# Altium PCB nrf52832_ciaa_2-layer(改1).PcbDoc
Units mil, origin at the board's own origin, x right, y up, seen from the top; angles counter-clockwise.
Board outline 354 x 353 mil, 2 copper layers (Top Layer, Bottom Layer), stack 11.8 mil thick; 15 components, 27 nets, 92 pads, 22 vias.
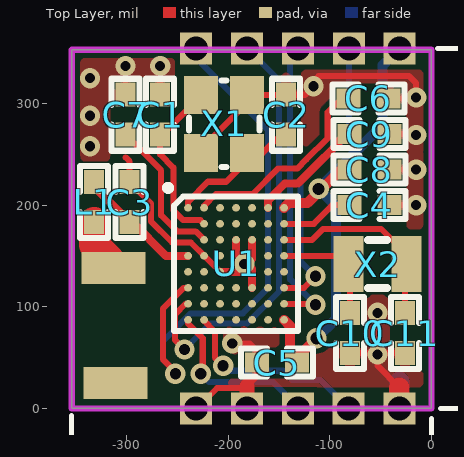
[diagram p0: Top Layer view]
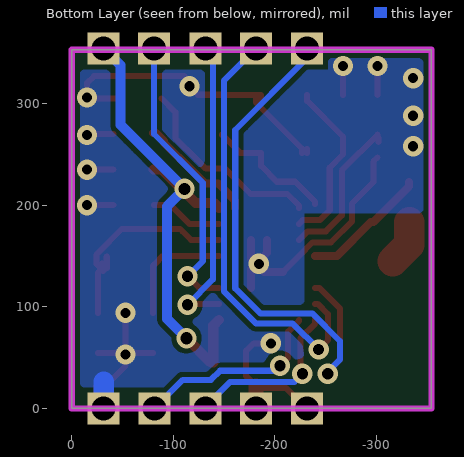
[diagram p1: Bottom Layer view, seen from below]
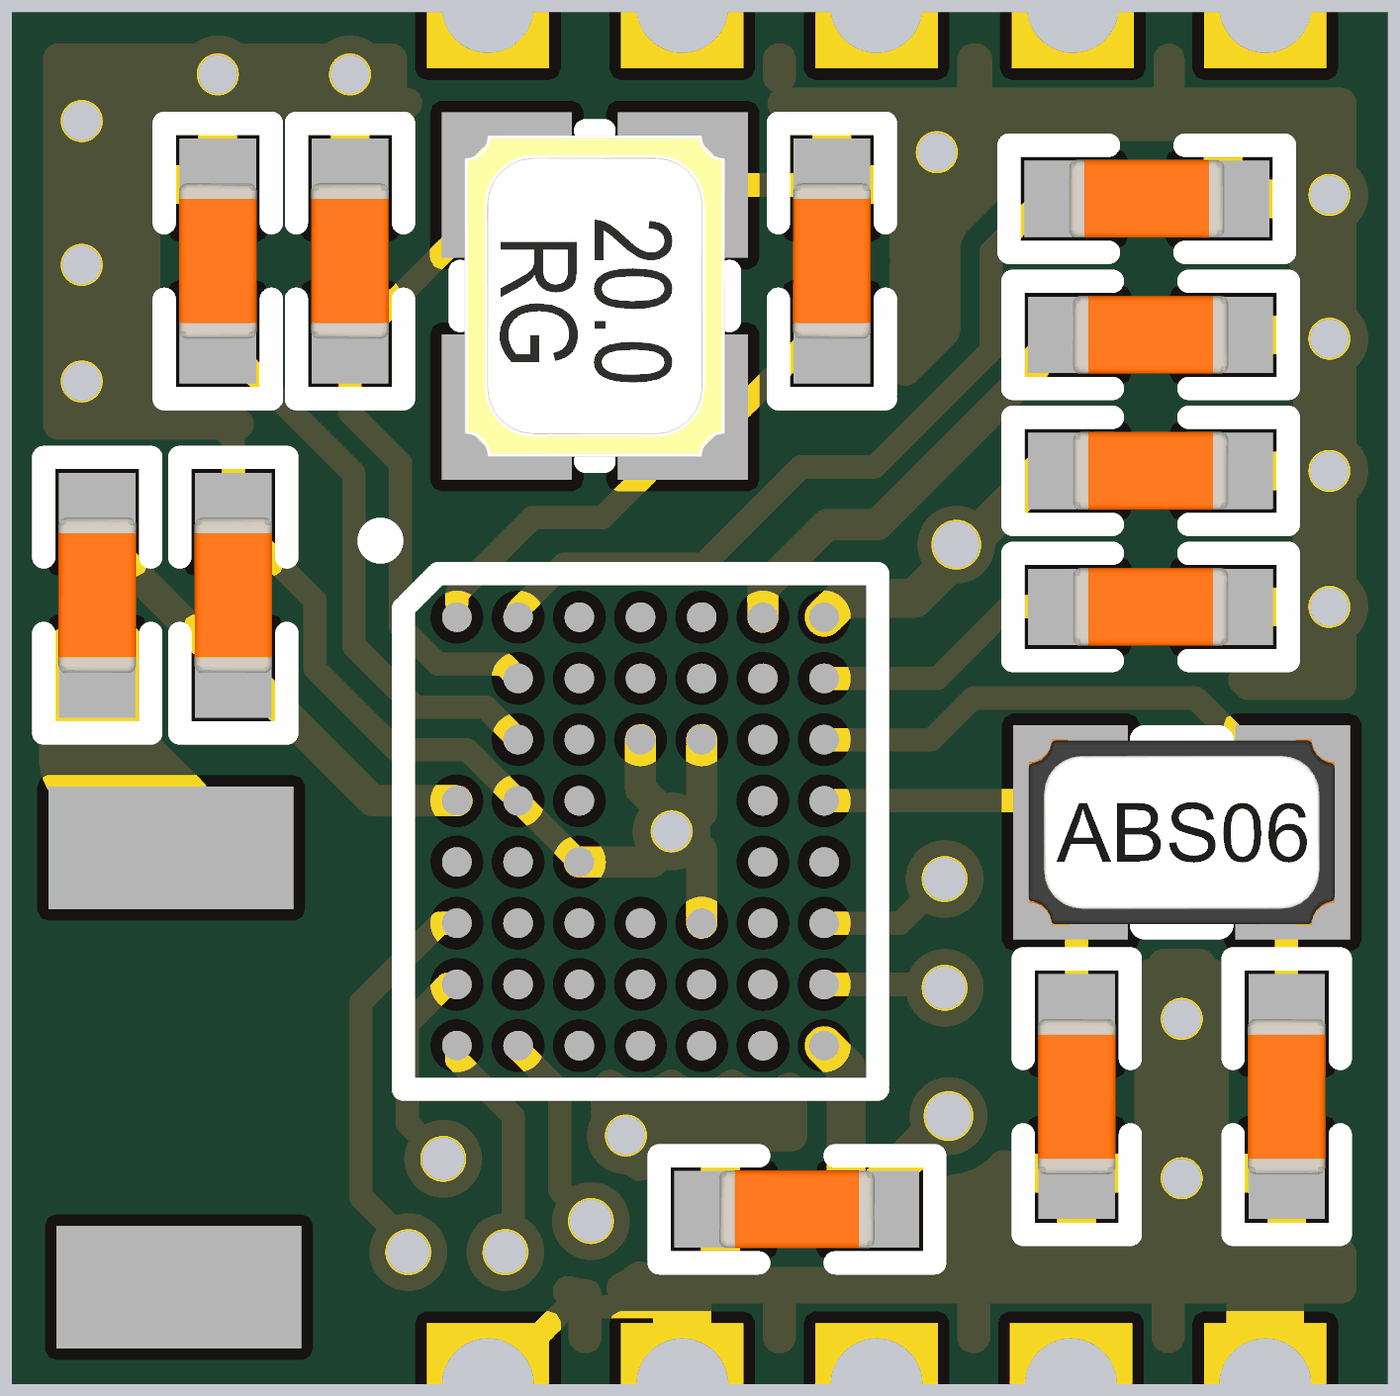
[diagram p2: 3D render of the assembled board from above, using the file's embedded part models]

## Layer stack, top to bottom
Top Layer: signal copper 1.4
Dielectric: core 9, FR-4, Dk 4.8
Bottom Layer: signal copper 1.4

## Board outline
-354,0 0,0 0,353 -354,353

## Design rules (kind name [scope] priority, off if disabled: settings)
Clearance Polygon_ANT [(InNamedPolygon('Top_Layer-GND')) or (InNamedPolygon('Bottom_Layer-GND')) vs InNet('RF')] p1: gap=5
Clearance Polygon [(InNamedPolygon('Top_Layer-GND')) or (InNamedPolygon('Bottom_Layer-GND')) or (InNamedPolygon('Mid_Layer_1-GND')) or (InNamedPolygon('Mid_Layer_2-GND'))] p2: gap=8
Clearance [All] p3: gap=5
ComponentClearance [All] p1 off: gap=10 collisioncheckmode=3 verticalgap=10 showdistances=FALSE
FabricationTestPointUsage TestPointUsage [All] p1: valid=0 allowmultiple=FALSE
FabricationTestpoint Testpoint [All] p1: side=3 testpointundercomponent=TRUE minsize=40 maxsize=100 preferedsize=60 minholesize=0 maxholesize=40 preferedholesize=32 testpointgrid=1 allowsidetop=TRUE allowsidebottom=TRUE usegrid=TRUE gridtolerance=0.01
Height [All] p1 off: minheight=0 maxheight=1000 prefheight=500
HoleSize [All] p1: absolutevalues=TRUE maxlimit=160 minlimit=3 maxpercent=80.000 minpercent=20.000
HoleToHoleClearance [All] p1 off: gap=3 allowstackedmicrovias=FALSE
MinimumAnnularRing [All] p1 off: minimumring=3.94
PolygonConnect PolygonConnect_1 [isVia and innet(gnd)] p1: connectstyle=Direct reliefconductorwidth=10 reliefentries=4 polygonreliefangle="90 Angle"
PolygonConnect [All] p2: connectstyle=Relief reliefconductorwidth=10 reliefentries=4 polygonreliefangle="90 Angle"
RoutingVias [All] p1: holewidth=16 width=32 viastyle="Through Hole" minholewidth=3.94 minwidth=9.84 maxholewidth=28 maxwidth=50
SilkscreenOverComponentPads [IsPad] p1: minsilkscreentomaskgap=10
SolderMaskExpansion [All] p1: expansion=3
Width [All] p1: maxlimit=100 minlimit=5 preferedwidth=6 minimp=50.000000 maximp=50.000000 favimp=50.000000
21 further rules are at their usual default settings.

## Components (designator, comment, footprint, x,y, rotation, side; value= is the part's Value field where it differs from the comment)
C1 "12pF" CAPC1005X04L -267,289 r270 top (schematic designator C8)
C2 "12pF" CAPC1005X04L -143,289 r270 top (schematic designator C8)
C3 "1.0pF" CAPC1005X04L -297,203 r270 top (schematic designator C8)
C4 "100nF" CAPC1005X04L -61,200 r0 top (schematic designator C8)
C5 "100nF" CAPC1005X04L -152,45 r180 top (schematic designator C8)
C6 "100pF" CAPC1005X04L -62,305 r180 top (schematic designator C8)
C7 "100pF" CAPC1005X04L -301,289 r90 top (schematic designator C8)
C8 "4.7µF" CAPC1005X04L -61,235 r0 top
C9 "1.0µF" CAPC1005X04L -61,270 r180 top (schematic designator C8)
C10 "12pF" CAPC1005X04L -80,74 r90 top (schematic designator C8)
C11 "12pF" CAPC1005X04L -26,74 r90 top (schematic designator C8)
L1 "3.3nH" CAPC1005X04L -332,203 r270 top (schematic designator C8)
U1 "nRF52832-CIAA" BGA50C40P7X8_295X322X50 -192.23,142.24 r0 top locked
X1 "32MHz" BT-XTAL_2016 -204,280 r270 top
X2 "32.768kHz" XTAL_2012 -53,142 r0 top

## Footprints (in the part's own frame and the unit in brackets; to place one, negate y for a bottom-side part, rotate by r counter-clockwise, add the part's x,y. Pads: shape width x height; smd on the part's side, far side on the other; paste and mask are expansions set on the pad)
BGA50C40P7X8_295X322X50 [mm] "BGA, 50-Leads, Body 2.95x3.22mmx0.50mm, Pitch 0.40mm"
  round 0.193 smd: A1(-1.2,1.4) A2(-0.8,1.4) A3(-0.4,1.4) A4(0,1.4) A5(0.4,1.4) A6(0.8,1.4) A7(1.2,1.4) B2(-0.8,1) B3(-0.4,1) B4(0,1) B5(0.4,1) B6(0.8,1) B7(1.2,1) C2(-0.8,0.6) C3(-0.4,0.6) C4(0,0.6) C5(0.4,0.6) C6(0.8,0.6) C7(1.2,0.6) D1(-1.2,0.2) D2(-0.8,0.2) D3(-0.4,0.2) D6(0.8,0.2) D7(1.2,0.2) E1(-1.2,-0.2) E2(-0.8,-0.2) E3(-0.4,-0.2) E6(0.8,-0.2) E7(1.2,-0.2) F1(-1.2,-0.6) F2(-0.8,-0.6) F3(-0.4,-0.6) F4(0,-0.6) F5(0.4,-0.6) F6(0.8,-0.6) F7(1.2,-0.6) G1(-1.2,-1) G2(-0.8,-1) G3(-0.4,-1) G4(0,-1) G5(0.4,-1) G6(0.8,-1) G7(1.2,-1) H1(-1.2,-1.4) H2(-0.8,-1.4) H3(-0.4,-1.4) H4(0,-1.4) H5(0.4,-1.4) H6(0.8,-1.4) H7(1.2,-1.4)
  silkscreen extent -1.75,-1.68 1.55,1.95, body extent -1.48,-1.61 1.48,1.61, height 0.51
BT-XTAL_2016 [mm] "Crystal 2.0 x 1.6 mm"
  rect 0.95x0.85 smd: 1(-0.725,-0.575) 2(0.725,-0.575) 3(0.725,0.575) 4(-0.725,0.575)
  silkscreen extent -1.08,-0.88 1.08,0.88, body extent -1.05,-0.85 1.05,0.85, height 0.56
CAPC1005X04L [mm] "Chip Capacitor, 2-Leads, Body 1.0x0.5mm, IPC High Density"
  rect 0.6x0.5 smd: 1(-0.5,0) 2(0.5,0)
  silkscreen extent -0.9,-0.35 0.9,0.35, body extent -0.51,-0.25 0.51,0.25, height 0.5
XTAL_2012 [mm] "XTAL SMD 2.0 x 1.2 mm"
  rect 0.75x1.4 smd: 1(-0.725,0) 2(0.725,0)
  silkscreen extent -0.24,-0.6 0.24,0.6, body extent -1,-0.61 1,0.61, height 0.6

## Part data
C1 C2 C3 C4 C5 C6 C7 C8 C9 C10 C11 L1: library part C0402-1?, "Capacitor, X5R, ?%"
U1: "Multi-protocol Bluetooth Low Energy, ANT and 2.4GHz proprietary system-on-chip"
X1: library part XTAL_SMD2016_32MHz_8pF_Epson, "XTAL SMD 2016, 32MHz, Cl=8pF, Total Tol: ?0ppm"
X2: library part XTAL_SMD2012_32.768kHz_9pF_Seiko, "XTAL SMD 2012, 32.768kHz, Cl=9pF, Total Tol: ?0ppm"

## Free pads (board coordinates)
  rect 62.99x31.5 smd: 0(-313,138) 0(-311,25)
  rect 31.5x31.5 hole 23.62: 1(-231.5,0) 2(-181.5,0) 3(-131.5,0) 4(-81.5,0) 5(-31.5,0) 6(-31.5,354.33) 7(-81,354.33) 8(-131.5,354.33) 9(-181.5,354.33) 10(-231.5,354.33)

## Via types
v1: diameter 20, hole 10, Top Layer to Bottom Layer, tented both sides, 14 vias
v2: diameter 20, hole 11, Top Layer to Bottom Layer, tented both sides, 6 vias
v3: diameter 20, hole 12, Top Layer to Bottom Layer, tented both sides, 2 vias

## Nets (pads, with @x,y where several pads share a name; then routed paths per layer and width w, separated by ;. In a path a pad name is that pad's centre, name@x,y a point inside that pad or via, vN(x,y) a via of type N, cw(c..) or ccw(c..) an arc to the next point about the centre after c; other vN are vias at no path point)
DEC1: C4.1 U1.B7 | length 71.6
  Top Layer w6: U1.B7 -115.82,181.61 -97.38,200.05 C4.1@-80.99,200.05
DEC2: C6.2 U1.A2 | length 195.9
  Top Layer w6: U1.A2 -223.73,199.27 -212,211 -176,211 -151,236 -132.01,236 -123.01,245 -102,266 -102,291.47 C6.2@-88.47,305
DEC3: C7.1 U1.C2 | length 150.4
  Top Layer w6: C7.1@-302,262 C7.1@-302,266.32 ; C7.1 -266,234.32 -266,190 -250.23,174.24 -232.11,174.24 U1.C2
DEC4: C9.2 U1.A6 | length 116.5
  Top Layer w8: U1.A6 -160.74,204.73 -144.28,221.19 -131.26,221.19 -118.46,234 -91,261.44 -91,263 -83,271 C9.2@-80,271
GND: C1.1 C2.1 C3.1 C4.2 C5.2 C6.1 C7.2 C8.2 C9.1 C10.1 C11.1 pad.1 pad.2 pad.5 U1.C4 U1.C5 U1.D2 U1.E3 U1.F5 X1.2 X1.4 | length 1060.3
  Top Layer w6: -301,247 -297,243 C3.1 -276,201.68 -276,184.1 -255.13,163.24 -236.86,163.24 U1.D2 U1.E3 ; C7.2 v1@-301,338 ; C1.1 v1@-267,338 ; X1.2@-231.64,251.46 X1.2@-231.64,255.36 ; pad.1 -231,0 -211,20 -182.5,20 ; X1.2 -226.64,255.61 -181.36,300.89 X1.4 ; v1(-196,64) -179,64 -171.68,56.68 C5.2 -171.68,31.81 -181.5,22 ; X1.4@-186.36,300.64 -186.36,308.54 X1.4 ; v1(-116,317) v1@-121,312 ; C10.1 v1@-54.32,54.32 ; v1(-53,94) v1(-53,53) ; C6.1 -15,305 -15,320 -22,327 -111,327 -121,317 v1@-121,312 ; C4.2 v1@-14,200 ; C8.2 v1@-14,235 ; C9.1 v1@-15,270 ; -31.5,20.5 -53,42 v1(-53,53) ; C11.1 -51.68,54.32 v1(-53,53) ; X1.4 -148.14,308.54 -148,308.68 C2.1 -124.32,308.68 v1@-121,312
  Top Layer w8: U1.E3 -189.23,134.36 v1@-181.36,142.24 ; U1.C4 -192.23,153.11 v1@-181.36,142.24 ; U1.F5 -176.49,137.36 v1@-181.36,142.24 ; U1.C5 -176.49,147.11 v1@-181.36,142.24
  Top Layer w15: pad.2 -181.5,22
  Top Layer w20: pad.5 -31.5,20.5
  Bottom Layer w20: pad.5 -31.5,26.19
  other v1: -184.23,142.24 -15,200 -15,235 -336,258 -15,269 -336,288 -15,306 -336,325 -301,337 -267,337
NetC3_2: C3.2 L1.1 U1.D1 | length 125.1
  Top Layer w8: L1.1 -332,218.31 C3.2 -294.31,183.31 -261.11,150.11 U1.D1
P0.00/XL1: C10.2 U1.D7 X2.1 | length 115.8
  Top Layer w6: U1.D7 -118,150.11 -89.66,150.11 X2.1 -80,140.46 C10.2
P0.01/XL2: C11.2 U1.C7 X2.2 | length 226.9
  Top Layer w6: U1.C7 -117.42,165.86 -109.05,174.24 -106.73,176.56 -49.44,176.56 -24.46,151.57 X2.2 ; X2.2@-34.46,149.46 -34.46,138 X2.2 ; X2.2@-31,135.46 X2.2@-29.45,137 ; X2.2@-29.69,142.69 -29.69,137.24 X2.2@-29.45,137 ; C11.2 -26,133.55 -27.23,134.78 X2.2@-29.45,137 ; X2.2@-29.45,137 X2.2
P0.05/AIN3: U1.E7
P0.06: pad.7 U1.F7 | length 290.6
  Top Layer w6: -140.53,118.62 U1.F7 -125.38,118.62 v2(-114,130)
  Bottom Layer w6: v2(-114,130) -129,145 -129,222.04 -81,270.04 pad.7
P0.08: pad.8 U1.G7 | length 300.4
  Top Layer w6: v2(-114,102) -114.87,102.87 U1.G7@-141.75,102.87 ; U1.G7@-141.75,102.87 U1.G7 U1.G7@-141.75,102.87
  Bottom Layer w6: pad.8 -139,346.83 -139,127 v2(-114,102)
P0.12: U1.H6
P0.14: U1.H5
P0.15: U1.H4
P0.16: U1.H3
P0.18: pad.4 U1.H2 | length 193.8
  Top Layer w6: U1.H2 -223.73,86.17 -213,75.44 -213,50 v2(-205,42)
  Bottom Layer w6: v2(-205,42) -200,37 -146,37 -137,28 -109.5,28 pad.4
P0.21: pad.3 U1.H1 | length 170.5
  Top Layer w6: U1.H1@-239.48,87.18 U1.H1 -239.48,83.48 -225,69 -225,36 v2(-227,34)
  Bottom Layer w6: v2(-227,34) -219,26 -156,26 -131.5,1.5 pad.3
P0.24: U1.E1
P0.28/AIN4: U1.A3
P0.29/AIN5: U1.A4
P0.30/AIN6: U1.A5
RF: L1.2 pad.0@-313,138 | length 44.9
  Top Layer w30: L1.2 -332,161 pad.0@-316,145
SWDCLK: pad.10 U1.F1 | length 529.6
  Top Layer w6: v2(-252,34) -252,36 -264.23,48.23 -264.23,98.24 -243.86,118.62 U1.F1
  Bottom Layer w6: v2(-252,34) -252,36 -264,48 -264,66.3 -236.8,93.5 -185.64,93.5 -161,118.14 -161,274 -231.5,344.5 pad.10
SWDIO: pad.9 U1.G1 | length 424.5
  Top Layer w6: v2(-243,58) -252.23,67.23 -252.23,92.66 -242.03,102.87 U1.G1
  Bottom Layer w6: v2(-243,58) -217.5,83.5 -181.5,83.5 -150,115 -150,322.83 pad.9
VDD_NRF: C5.1 C8.1 pad.6 U1.A7 U1.H7 | length 494
  Top Layer w10: U1.H7 -139.31,81.44 -139.31,45 -137,45 v3(-113,69) ; U1.A7 -140.11,202.24 -121.76,202.24 -89,235 C8.1
  Bottom Layer w10: v3(-113,69) -93.78,88.22 -93.78,198.78 v3(-111,216) -48,279 -48,337.83 pad.6
XC1: C1.2 U1.B2 X1.1 | length 169.4
  Top Layer w6: X1.1@-231.64,308.54 -231.64,302.68 -267,267.31 -267,250 -254,237 -254,195 -244.23,185.24 -227.36,185.24 U1.B2
XC2: C2.2 U1.A1 X1.3 | length 128.8
  Top Layer w6: U1.A1@-239.48,201 -239.48,203.52 -220,223 -202,223 -186.36,238.64 -186.36,251.46 -165.86,251.46 C2.2@-148,269.31
pads on no net: U1.B3 U1.B4 U1.B5 U1.B6 U1.C3 U1.C6 U1.D3 U1.D6 U1.E2 U1.E6 U1.F2 U1.F3 U1.F4 U1.F6 U1.G2 U1.G3 U1.G4 U1.G5 U1.G6

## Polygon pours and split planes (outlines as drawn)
GND on Top Layer "Top Layer-No Net" (hatched 90Degree grid 1 track 8, remove dead copper, pour order 28): -354,0 0,0 0,354 -354,354
GND on Bottom Layer "Top Layer-No Net" (hatched 90Degree grid 1 track 8, remove dead copper, pour order 30): -354,0 0,0 0,353 -354,353

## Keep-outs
Keep-Out Layer:
  the board outline again, w6

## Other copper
Top Layer:
  pour cut-out: -98,180 -8,180 -8,108 -98,108
  pour cut-out: -234,192 -144,192 -144,87 -234,87
  pour cut-out: -249,333 -159,333 -159,228 -249,228
  pour cut-out: -198,220 -275,220 -275,247 -352,247 -352,0 -262,0 -262,104 -198.25,104
Bottom Layer:
  pour cut-out: -354,0 -225,0 -225,196 -354,196

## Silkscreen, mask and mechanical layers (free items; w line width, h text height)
Top Overlay:
  lines w5: -354.33,-140 -354.33,-7 ; 0,-143 0,-10 ; 6,354.33 139,354.33 ; 9,0 142,0
  lines w10: -454.33,-140 -354.33,-140 ; -414.33,-160 -354.33,-140 ; -414.33,-120 -354.33,-140 ; -354.33,-150 -354.33,-130 ; 0,-150 0,-130 ; 60,-160 0,-140 ; 60,-120 0,-140 ; 100,-140 0,-140 ; 119,-60 139,0 ; 119,414.33 139,354.33 ; 129,0 149,0 ; 129,354.33 149,354.33 ; 139,-100 139,0 ; 139,454.33 139,354.33 ; 159,-60 139,0 ; 159,414.33 139,354.33
  text "354.331 (mil)" at 282.96,-173.72 h60 r90
  text "354.331 (mil)" at -528.05,-283.96 h60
